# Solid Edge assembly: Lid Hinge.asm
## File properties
Author: m_hel
Template: Iso Metric Assembly.asm
Last saved by: m_hel
Revision: 2
Application: Solid Edge
Username: m_hel
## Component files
Hinge.psm
Hinge Bolt.par
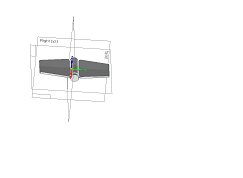
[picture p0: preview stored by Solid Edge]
